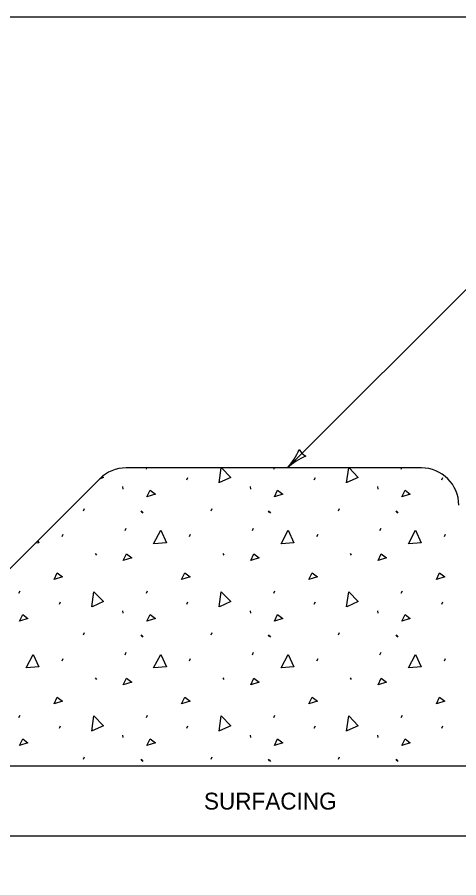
# Model space of a CAD drawing. Extents: x 49991.4 to 50021, y 49987.6 to 50011.4.
# Drawn here: x 50004.343 to 50005.916, y 50008.196 to 50011.263 of the extents above; entities that cross this region are included whole.
import ezdxf

# ---------------------------------------------------------------- set-up
doc = ezdxf.new("R2010")
doc.units = 0
for name, color, linetype in [('Level 1', 7, 'Continuous'), ('Level 2', 7, 'Continuous'), ('Level 3', 7, 'Continuous')]:
    doc.layers.add(name, color=color, linetype=linetype)

msp = doc.modelspace()

# ---------------------------------------------------------------- linework, layer by layer
at = {"layer": 'Level 1'}
for p, q in [((50005.7827, 50009.6568), (50004.7309, 50009.6568)), ((50004.8032, 50009.6526), (50004.8051, 50009.6568)), ((50005.257, 50009.6526), (50005.2589, 50009.6568)), ((50005.7108, 50009.6526), (50005.7127, 50009.6568)), ((50004.637, 50009.6178), (50003.9828, 50008.9636)), ((50004.9472, 50009.6137), (50004.951, 50009.6223)), ((50005.401, 50009.6137), (50005.4048, 50009.6223)), ((50005.8548, 50009.6137), (50005.8586, 50009.6223)), ((50004.7186, 50009.5899), (50004.7196, 50009.5814)), ((50005.1724, 50009.5899), (50005.1734, 50009.5814)), ((50005.6262, 50009.5899), (50005.6272, 50009.5814)), ((50004.5796, 50009.5038), (50004.5834, 50009.5124)), ((50005.0334, 50009.5038), (50005.0372, 50009.5124)), ((50005.4872, 50009.5038), (50005.491, 50009.5124)), ((50004.7833, 50009.5038), (50004.7871, 50009.4982)), ((50004.7871, 50009.5017), (50004.7909, 50009.496)), ((50005.2371, 50009.5038), (50005.2409, 50009.4982)), ((50005.2409, 50009.5017), (50005.2447, 50009.496)), ((50005.6909, 50009.5038), (50005.6947, 50009.4982)), ((50005.6947, 50009.5017), (50005.6985, 50009.496)), ((50004.5029, 50009.4118), (50004.5067, 50009.4204)), ((50004.7274, 50009.4336), (50004.7312, 50009.4421)), ((50004.9567, 50009.4118), (50004.9605, 50009.4204)), ((50005.1812, 50009.4336), (50005.185, 50009.4421)), ((50005.4105, 50009.4118), (50005.4143, 50009.4204)), ((50005.635, 50009.4336), (50005.6388, 50009.4421)), ((50005.8643, 50009.4118), (50005.8681, 50009.4204)), ((50004.6213, 50009.3512), (50004.6251, 50009.3455)), ((50005.0751, 50009.3512), (50005.0789, 50009.3455)), ((50005.5289, 50009.3512), (50005.5327, 50009.3455)), ((50004.3494, 50009.21), (50004.3532, 50009.2186)), ((50004.8032, 50009.21), (50004.807, 50009.2186)), ((50005.257, 50009.21), (50005.2608, 50009.2186)), ((50005.7108, 50009.21), (50005.7146, 50009.2186)), ((50004.4934, 50009.1712), (50004.4972, 50009.1797)), ((50004.9472, 50009.1712), (50004.951, 50009.1797)), ((50005.401, 50009.1712), (50005.4048, 50009.1797)), ((50005.8548, 50009.1712), (50005.8586, 50009.1797)), ((50004.7186, 50009.1474), (50004.7196, 50009.1389)), ((50005.1724, 50009.1474), (50005.1734, 50009.1389)), ((50005.6262, 50009.1474), (50005.6272, 50009.1389)), ((50004.5796, 50009.0613), (50004.5834, 50009.0698)), ((50004.7833, 50009.0613), (50004.7871, 50009.0556)), ((50004.7871, 50009.0592), (50004.7909, 50009.0535)), ((50005.0334, 50009.0613), (50005.0372, 50009.0698)), ((50005.2371, 50009.0613), (50005.2409, 50009.0556)), ((50005.2409, 50009.0592), (50005.2447, 50009.0535)), ((50005.4872, 50009.0613), (50005.491, 50009.0698)), ((50005.6909, 50009.0613), (50005.6947, 50009.0556)), ((50005.6947, 50009.0592), (50005.6985, 50009.0535)), ((50004.7274, 50008.9911), (50004.7312, 50008.9996)), ((50005.1812, 50008.9911), (50005.185, 50008.9996)), ((50005.635, 50008.9911), (50005.6388, 50008.9996)), ((50004.5029, 50008.9693), (50004.5067, 50008.9778)), ((50004.9567, 50008.9693), (50004.9605, 50008.9778)), ((50005.4105, 50008.9693), (50005.4143, 50008.9778)), ((50005.8643, 50008.9693), (50005.8681, 50008.9778)), ((50004.6213, 50008.9087), (50004.6251, 50008.903)), ((50005.0751, 50008.9087), (50005.0789, 50008.903)), ((50005.5289, 50008.9087), (50005.5327, 50008.903)), ((50004.3494, 50008.7675), (50004.3532, 50008.776)), ((50004.8032, 50008.7675), (50004.807, 50008.776)), ((50005.257, 50008.7675), (50005.2608, 50008.776)), ((50005.7108, 50008.7675), (50005.7146, 50008.776)), ((50004.4934, 50008.7287), (50004.4972, 50008.7372)), ((50004.9472, 50008.7287), (50004.951, 50008.7372)), ((50005.401, 50008.7287), (50005.4048, 50008.7372)), ((50005.8548, 50008.7287), (50005.8586, 50008.7372)), ((50004.7186, 50008.7049), (50004.7196, 50008.6964)), ((50005.1724, 50008.7049), (50005.1734, 50008.6964)), ((50005.6262, 50008.7049), (50005.6272, 50008.6964)), ((50004.5796, 50008.6188), (50004.5834, 50008.6273)), ((50005.0334, 50008.6188), (50005.0372, 50008.6273)), ((50005.4872, 50008.6188), (50005.491, 50008.6273)), ((50005.9155, 50008.5943), (50003.7905, 50008.5943)), ((50006.8155, 50008.5943), (50004.4155, 50008.5943)), ((50004.7833, 50008.6188), (50004.7871, 50008.6131)), ((50004.7871, 50008.6166), (50004.7909, 50008.6109)), ((50005.2371, 50008.6188), (50005.2409, 50008.6131)), ((50005.2409, 50008.6166), (50005.2447, 50008.6109)), ((50005.6909, 50008.6188), (50005.6947, 50008.6131)), ((50005.6947, 50008.6166), (50005.6985, 50008.6109)), ((50006.8155, 50008.3444), (50003.6881, 50008.3444))]:
    msp.add_line(p, q, dxfattribs=at)
msp.add_lwpolyline([(50008.6146, 50011.2628), (50000.3356, 50011.2628), (50000.3356, 50000.0624), (50008.6146, 50000.0624)], close=True, dxfattribs=at)
for points in [[(50005.0625, 50009.6039), (50005.0698, 50009.6568)], [(50005.0712, 50009.6568), (50005.1039, 50009.623), (50005.0633, 50009.6042)], [(50005.5163, 50009.6039), (50005.5236, 50009.6568)], [(50005.525, 50009.6568), (50005.5577, 50009.623), (50005.5171, 50009.6042)], [(50004.6474, 50009.6258), (50004.6501, 50009.623), (50004.6353, 50009.6162)], [(50004.8051, 50009.5531), (50004.8165, 50009.5768), (50004.8354, 50009.5626), (50004.8051, 50009.5531)], [(50005.2589, 50009.5531), (50005.2703, 50009.5768), (50005.2892, 50009.5626), (50005.2589, 50009.5531)], [(50005.7127, 50009.5531), (50005.7241, 50009.5768), (50005.743, 50009.5626), (50005.7127, 50009.5531)], [(50004.8288, 50009.3862), (50004.8544, 50009.4346), (50004.8743, 50009.39), (50004.8297, 50009.3862)], [(50005.2826, 50009.3862), (50005.3082, 50009.4346), (50005.3281, 50009.39), (50005.2835, 50009.3862)], [(50005.7364, 50009.3862), (50005.762, 50009.4346), (50005.7819, 50009.39), (50005.7373, 50009.3862)], [(50004.417, 50009.3978), (50004.4205, 50009.39), (50004.4081, 50009.389)], [(50004.7208, 50009.3266), (50004.7321, 50009.3502), (50004.7511, 50009.336), (50004.7208, 50009.3266)], [(50005.1746, 50009.3266), (50005.1859, 50009.3502), (50005.2049, 50009.336), (50005.1746, 50009.3266)], [(50005.6284, 50009.3266), (50005.6397, 50009.3502), (50005.6587, 50009.336), (50005.6284, 50009.3266)], [(50004.4747, 50009.2588), (50004.486, 50009.2825), (50004.505, 50009.2683), (50004.4747, 50009.2588)], [(50004.9285, 50009.2588), (50004.9398, 50009.2825), (50004.9588, 50009.2683), (50004.9285, 50009.2588)], [(50005.3822, 50009.2588), (50005.3936, 50009.2825), (50005.4126, 50009.2683), (50005.3822, 50009.2588)], [(50005.836, 50009.2588), (50005.8474, 50009.2825), (50005.8664, 50009.2683), (50005.836, 50009.2588)], [(50004.6087, 50009.1614), (50004.6162, 50009.2155), (50004.6501, 50009.1805), (50004.6096, 50009.1617)], [(50005.0625, 50009.1614), (50005.07, 50009.2155), (50005.1039, 50009.1805), (50005.0633, 50009.1617)], [(50005.5163, 50009.1614), (50005.5238, 50009.2155), (50005.5577, 50009.1805), (50005.5171, 50009.1617)], [(50004.3513, 50009.1106), (50004.3627, 50009.1343), (50004.3816, 50009.12), (50004.3513, 50009.1106)], [(50004.8051, 50009.1106), (50004.8165, 50009.1343), (50004.8354, 50009.12), (50004.8051, 50009.1106)], [(50005.2589, 50009.1106), (50005.2703, 50009.1343), (50005.2892, 50009.12), (50005.2589, 50009.1106)], [(50005.7127, 50009.1106), (50005.7241, 50009.1343), (50005.743, 50009.12), (50005.7127, 50009.1106)], [(50004.375, 50008.9437), (50004.4006, 50008.992), (50004.4205, 50008.9475), (50004.3759, 50008.9437)], [(50004.8288, 50008.9437), (50004.8544, 50008.992), (50004.8743, 50008.9475), (50004.8297, 50008.9437)], [(50005.2826, 50008.9437), (50005.3082, 50008.992), (50005.3281, 50008.9475), (50005.2835, 50008.9437)], [(50005.7364, 50008.9437), (50005.762, 50008.992), (50005.7819, 50008.9475), (50005.7373, 50008.9437)], [(50004.7208, 50008.884), (50004.7321, 50008.9077), (50004.7511, 50008.8935), (50004.7208, 50008.884)], [(50005.1746, 50008.884), (50005.1859, 50008.9077), (50005.2049, 50008.8935), (50005.1746, 50008.884)], [(50005.6284, 50008.884), (50005.6397, 50008.9077), (50005.6587, 50008.8935), (50005.6284, 50008.884)], [(50004.4747, 50008.8163), (50004.486, 50008.84), (50004.505, 50008.8258), (50004.4747, 50008.8163)], [(50004.9285, 50008.8163), (50004.9398, 50008.84), (50004.9588, 50008.8258), (50004.9285, 50008.8163)], [(50005.3822, 50008.8163), (50005.3936, 50008.84), (50005.4126, 50008.8258), (50005.3822, 50008.8163)], [(50005.836, 50008.8163), (50005.8474, 50008.84), (50005.8664, 50008.8258), (50005.836, 50008.8163)], [(50004.6087, 50008.7189), (50004.6162, 50008.773), (50004.6501, 50008.738), (50004.6096, 50008.7192)], [(50005.0625, 50008.7189), (50005.07, 50008.773), (50005.1039, 50008.738), (50005.0633, 50008.7192)], [(50005.5163, 50008.7189), (50005.5238, 50008.773), (50005.5577, 50008.738), (50005.5171, 50008.7192)], [(50004.3513, 50008.668), (50004.3627, 50008.6917), (50004.3816, 50008.6775), (50004.3513, 50008.668)], [(50004.8051, 50008.668), (50004.8165, 50008.6917), (50004.8354, 50008.6775), (50004.8051, 50008.668)], [(50005.2589, 50008.668), (50005.2703, 50008.6917), (50005.2892, 50008.6775), (50005.2589, 50008.668)], [(50005.7127, 50008.668), (50005.7241, 50008.6917), (50005.743, 50008.6775), (50005.7127, 50008.668)]]:
    msp.add_lwpolyline(points, dxfattribs=at)
for centre, start, end in [((50004.7309, 50009.524), 90, 135), ((50005.7827, 50009.524), 0, 90)]:
    msp.add_arc(centre, 0.1328, start, end, dxfattribs=at)
at = {"layer": 'Level 3'}
msp.add_line((50005.3054, 50009.6568), (50006.3644, 50010.7158), dxfattribs=at)
for centre, radius, start, end in [((50005.1327, 50009.8132), 0.233, 317.8273, 337.0772), ((50005.456, 50009.4932), 0.2223, 112.456, 132.6395), ((50005.396, 50009.7475), 0.0548, 207.1388, 242.8612)]:
    msp.add_arc(centre, radius, start, end, dxfattribs=at)

# ---------------------------------------------------------------- texts
at = {"layer": 'Level 2'}
msp.add_text('SURFACING', height=0.06, dxfattribs=at).set_placement((50005.0082, 50008.4393))

doc.saveas('drawing.dxf')
